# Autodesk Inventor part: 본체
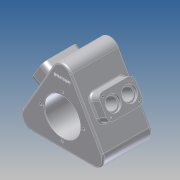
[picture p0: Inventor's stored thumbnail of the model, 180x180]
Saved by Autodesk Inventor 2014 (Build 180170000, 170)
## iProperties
Company: 한국ATC센터
Created: 2014-01
Part Number: 본체
Document SubType Name: Modeling
Designer: KYOUNG IL JANG
Density: 1 g/cm^3
Material: 일반
Mass: 657.987 g
Surface Area: 1165.97 cm^2
Volume: 657.987 cm^3
Vendor: CBT Solutions
Appearance: 기본값
Author: KYOUNG IL JANG
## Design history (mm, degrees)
sketch "스케치1"
  geometry: C1 r 75 at (0, 0); C2 r 47.5 at (0, 0); 1 further point
  constraints: 2 centre point, 2 coincident
  dimensions: "d0" = 150 diameter of C1; "d1" = 95 diameter of C2
extrude "돌출1" new body sketch "스케치1" distance "d2" = 95; taper "d3" = 0 deg
node "작업 평면1"
  node "작업 평면3"
sketch "스케치2"
  geometry: L1 (95, 47.5)-(95, -47.5) reference; L2 (0, 47.5)-(0, -47.5) reference; L3 (0, -22.5)-(70, -22.5); L4 (70, -22.5)-(70, 22.5); L5 (70, 22.5)-(0, 22.5); 3 further points
  constraints: 6 end point, 3 perpendicular, 2 midpoint, 2 point on line, 1 horizontal alignment
  dimensions: "d5" = 45 distance of L3.end L4.end; "d104" = 70 distance of L4.end L5.end
extrude "돌출2" join sketch "스케치2" stored distance "d7" = 100; taper "d8" = 0 deg
fillet "모깎기1" dims "d9" = 10
sketch "스케치3"
  geometry: L1 (60.622, -55)-(-60.622, -55); L2 (-77.942, -25)-(-17.321, 80); L3 (17.321, 80)-(77.942, -25); A1 r 20 centre (-60.622, -35) between (-77.942, -25) and (-60.622, -55); A2 r 20 centre (0, 70) between (17.321, 80) and (-17.321, 80); A3 r 20 centre (60.622, -35) between (60.622, -55) and (77.942, -25); 5 further points
  constraints: 6 end point, 6 point on circle, 6 point on line, 6 tangent, 3 centre point, 2 equal radius, 1 coincident, 1 horizontal, 7 other
  dimensions: "d14" = 20 radius of A1; "d15" = 55 distance from line of L2 point (0, 0)
extrude "돌출3" join sketch "스케치3" distance "d16" = 15; taper "d17" = 0 deg
extrude "돌출9" join sketch "스케치3" distance "d100" = 80; taper "d101" = 0 deg
fillet "모깎기3" dims "d19" = 3
sketch "스케치4"
  geometry: C1 r 47.5 at (0, 0) reference; C2 r 32.5 at (0, 0); 1 further point
  constraints: 1 centre point, 1 coincident
  dimensions: "d20" = 65 diameter of C2
extrude "돌출4" cut sketch "스케치4" distance "d21" = 15; taper "d22" = 0 deg
fillet "모깎기4" dims "d23" = 3
sketch "스케치5"
  geometry: C1 r 35 at (0, 0); 1 further point
  constraints: 1 centre point, 1 coincident
  dimensions: "d25" = 70 diameter of C1
extrude "돌출5" cut sketch "스케치5" distance "d26" = 85; taper "d27" = 0 deg
sketch "스케치6"
  geometry: L1 (0, 12.5)-(0, -12.5) reference; 3 further points
  constraints: 2 horizontal alignment, 1 midpoint
  dimensions: "d108" = 20 distance from line of point (20, 0) L1; "d109" = 32 distance of point (52, 0) point (20, 0)
hole "구멍1" sketch "스케치6" at (20, 0), (52, 0) diameter "d30" = 22; stored, may be unused: countersink angle "d34" = 90 deg, drill point angle "d36" = 118 deg; dims "d31" = 6, "d32" = 28, "d33" = 5, "d35" = 8
node "작업 평면2"
sketch "스케치8"
  geometry: C1 r 18.5 at (0, 0); 1 further point
  constraints: 1 centre point, 1 coincident
  dimensions: "d44" = 37 diameter of C1
extrude "돌출7" cut sketch "스케치8" distance "d45" = 17; taper "d46" = 0 deg
sketch "스케치9"
  geometry: C1 r 13 at (0, 0); 1 further point
  constraints: 1 centre point, 1 coincident
  dimensions: "d47" = 26 diameter of C1
extrude "돌출8" cut sketch "스케치9" distance "d48" = 2; taper "d49" = 0 deg
fillet "모깎기6" dims "d50" = 3, "d51" = 0.3
chamfer "모따기1" distance "d52" = 1; stored, may be unused: second distance "d53" = 2, angle "d54" = 45 deg
sketch "스케치10"
  geometry: L1 (0, 12.5)-(0, -12.5) reference; A1 r 10 centre (60, -12.5) between (60, -22.5) and (70, -12.5) reference; 5 further points
  constraints: 2 horizontal alignment, 2 vertical alignment
  dimensions: "d58" = 7.5 distance from line of point (7.5, -16) L1; "d105" = 56 distance of point (7.5, -16) point (63.5, -16); "d106" = 32 distance of point (7.5, -16) point (7.5, 16); "d107" = 16 vertical distance of point (0, 0) point (7.5, -16) (= 0.5 x d106)
hole "구멍2" sketch "스케치10" at (7.5, -16), (63.5, -16), (63.5, 16), (7.5, 16) diameter "d59" = 3.242; stored, may be unused: countersink angle "d63" = 90 deg, drill point angle "d65" = 118 deg; dims "d60" = 10, "d61" = 4, "d62" = 2, "d64" = 13
sketch "스케치11" dims "d1" = 95
  geometry: C1 r 3.3 at (0, 42); C2 r 3.3 at (-34.641, -20) reference; C3 r 3.3 at (34.641, -20) reference; 1 further point
  constraints: 1 centre point, 1 vertical alignment
  dimensions: "d96" = 42 distance of point (0, 0) C1.centre
hole "구멍3" sketch "스케치11" at (0, 42) diameter "d72" = 5.242; stored, may be unused: countersink angle "d76" = 90 deg, drill point angle "d78" = 118 deg; dims "d73" = 12, "d74" = 4, "d75" = 2, "d77" = 15
chamfer "모따기2" distance "d93" = 1; stored, may be unused: second distance "d94" = 2, angle "d95" = 45 deg
sketch "스케치14"
  geometry: C1 r 36 at (0, 0) reference; 1 further point
  constraints: 1 vertical alignment, 1 other
  dimensions: "d110" = 65 distance of C1.centre point (0, 65)
feature "엠보싱2" sketch "스케치14" dims "d0" = 150, "d1" = 95, "d14" = 20, "d15" = 55, "d98" = 0.5, "d99" = 0
node "솔리드1"
pattern_circular "원형 패턴1" dims angle "d11" = 120 deg
pattern_circular "원형 패턴4" dims angle "d70" = 120 deg
pattern_circular "원형 패턴3" dims angle "d67" = 360 deg
pattern_circular "원형 패턴5" dims angle "d80" = 360 deg
node "투영된 루프1"
node "투영된 루프2"
node "참조2"
node "참조3"
other parameters: "d102" = 120 deg, "d103" = -75
